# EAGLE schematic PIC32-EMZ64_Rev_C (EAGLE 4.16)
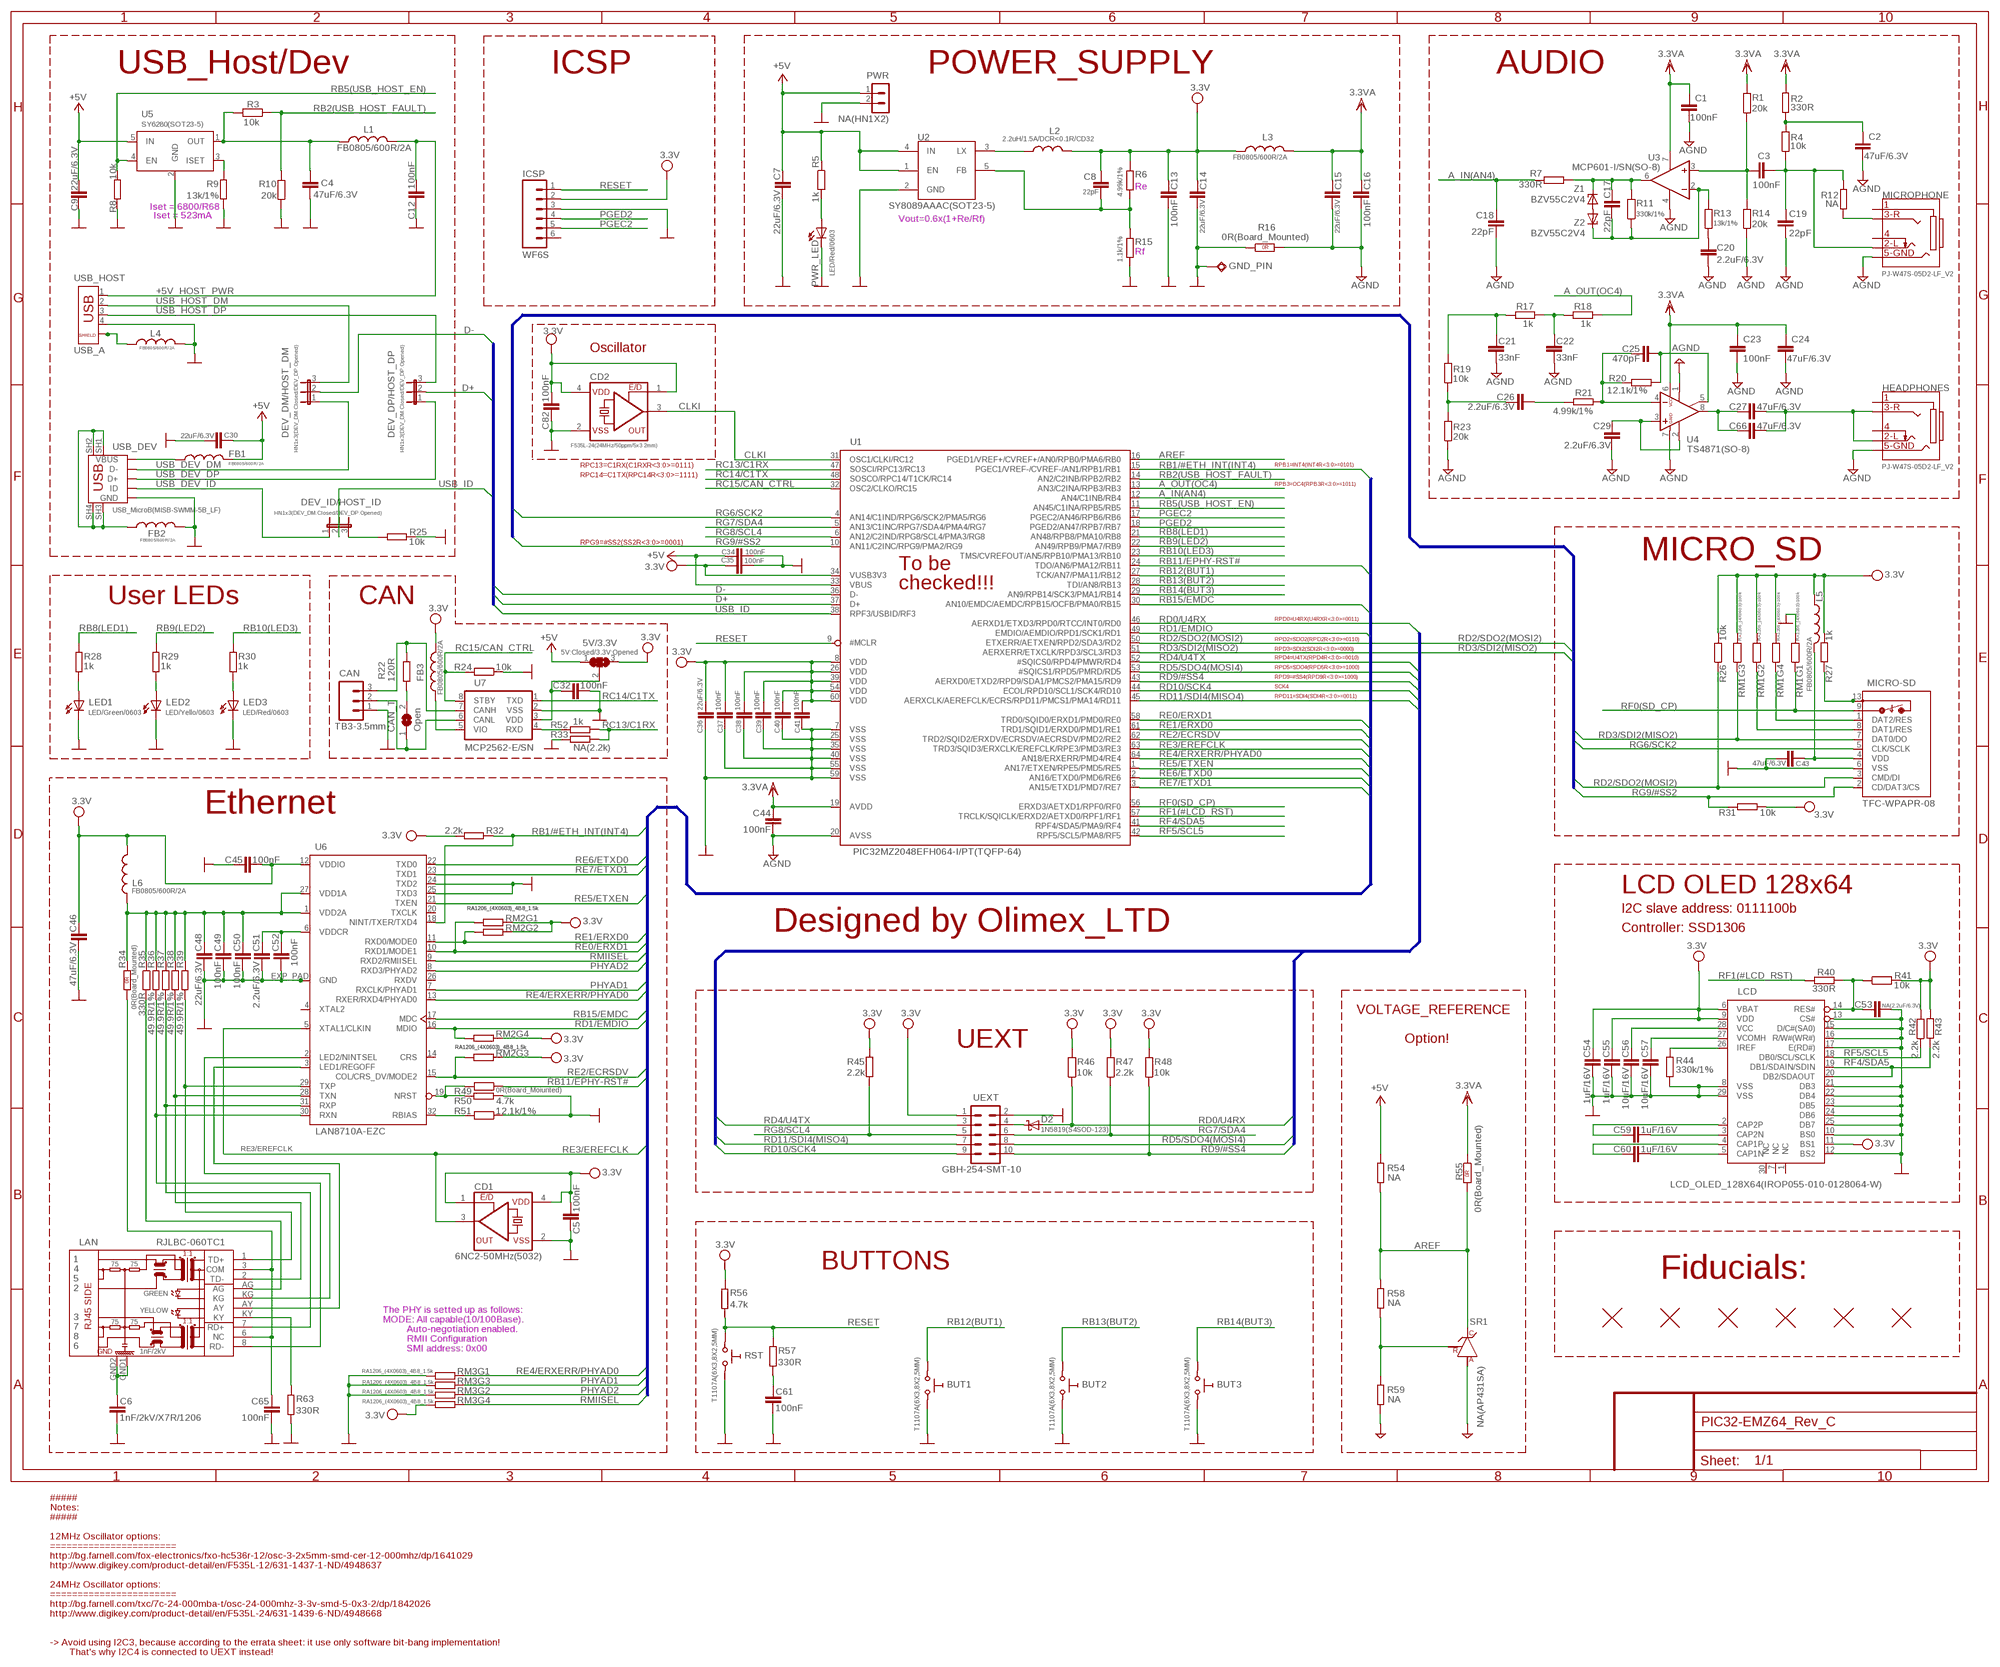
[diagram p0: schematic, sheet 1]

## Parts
5V/3.3V  5V:Closed/3.3V:Opened  SJ2W7  [SJ_2_SMALLER_12_TIED]
BUT1  T1107A(6X3,8X2,5MM)  SW-TAKTT1107A(6X3,8X2,5MM)  [WS-TAKT_6X3.5_SMD_NOCREAM]
BUT2  T1107A(6X3,8X2,5MM)  SW-TAKTT1107A(6X3,8X2,5MM)  [WS-TAKT_6X3.5_SMD_NOCREAM]
BUT3  T1107A(6X3,8X2,5MM)  SW-TAKTT1107A(6X3,8X2,5MM)  [WS-TAKT_6X3.5_SMD_NOCREAM]
C1  100nF  C-EUC0402_SMALL  [C0402_SMALL]
C2  47uF/6.3V  C-EUC0805_5MIL_DWS  [C0805_5MIL_DWS]
C3  100nF  C-EUC0402_SMALL  [C0402_SMALL]
C4  47uF/6.3V  C-EUC0805_5MIL_DWS  [C0805_5MIL_DWS]
C5  100nF  C-EUC0402_SMALL  [C0402_SMALL]
C6  1nF/2kV/X7R/1206  C-EUC1206_5MILS_WS_ISO  [C1206_5MILS_WS_ISO]
C7  22uF/6.3V  C-EUC0603_DWS  [C0603_DWS]
C8  22pF  C-EUC0402_SMALL  [C0402_SMALL]
C9  22uF/6.3V  C-EUC0603_DWS  [C0603_DWS]
C12  100nF  C-EUC0402_SMALL  [C0402_SMALL]
C13  100nF  C-EUC0402_SMALL  [C0402_SMALL]
C14  22uF/6.3V  C-EUC0603_DWS  [C0603_DWS]
C15  22uF/6.3V  C-EUC0603_DWS  [C0603_DWS]
C16  100nF  C-EUC0402_SMALL  [C0402_SMALL]
C17  22pF  C-EUC0402_SMALL  [C0402_SMALL]
C18  22pF  C-EUC0402_SMALL  [C0402_SMALL]
C19  22pF  C-EUC0402_SMALL  [C0402_SMALL]
C20  2.2uF/6.3V  C-EUC0603_DWS  [C0603_DWS]
C21  33nF  C-EUC0402_SMALL  [C0402_SMALL]
C22  33nF  C-EUC0402_SMALL  [C0402_SMALL]
C23  100nF  C-EUC0402_SMALL  [C0402_SMALL]
C24  47uF/6.3V  C-EUC0805_5MIL_DWS  [C0805_5MIL_DWS]
C25  470pF  C-EUC0603_DWS  [C0603_DWS]
C26  2.2uF/6.3V  C-EUC0603_DWS  [C0603_DWS]
C27  47uF/6.3V  C-EUC0805_5MIL_DWS  [C0805_5MIL_DWS]
C29  2.2uF/6.3V  C-EUC0603_DWS  [C0603_DWS]
C30  22uF/6.3V  C-EUC0603_DWS  [C0603_DWS]
C32  100nF  C-EUC0402_SMALL  [C0402_SMALL]
C34  100nF  C-EUC0402_SMALL  [C0402_SMALL]
C35  100nF  C-EUC0402_SMALL  [C0402_SMALL]
C36  22uF/6.3V  C-EUC0603_DWS  [C0603_DWS]
C37  100nF  C-EUC0402_SMALL  [C0402_SMALL]
C38  100nF  C-EUC0402_SMALL  [C0402_SMALL]
C39  100nF  C-EUC0402_SMALL  [C0402_SMALL]
C40  100nF  C-EUC0402_SMALL  [C0402_SMALL]
C41  100nF  C-EUC0402_SMALL  [C0402_SMALL]
C43  47uF/6.3V  C-EUC0805_5MIL_DWS  [C0805_5MIL_DWS]
C44  100nF  C-EUC0402_SMALL  [C0402_SMALL]
C45  100nF  C-EUC0402_SMALL  [C0402_SMALL]
C46  47uF/6.3V  C-EUC0805_5MIL_DWS  [C0805_5MIL_DWS]
C48  22uF/6.3V  C-EUC0603_DWS  [C0603_DWS]
C49  100nF  C-EUC0402_SMALL  [C0402_SMALL]
C50  100nF  C-EUC0402_SMALL  [C0402_SMALL]
C51  2.2uF/6.3V  C-EUC0603_DWS  [C0603_DWS]
C52  100nF  C-EUC0402_SMALL  [C0402_SMALL]
C53  NA(2.2uF/6.3V)  C-EUC0603_DWS  [C0603_DWS]
C54  1uF/16V  C-EUC0805_5MIL_DWS  [C0805_5MIL_DWS]
C55  1uF/16V  C-EUC0805_5MIL_DWS  [C0805_5MIL_DWS]
C56  10uF/16V  C-EUC0805_5MIL_DWS  [C0805_5MIL_DWS]
C57  10uF/16V  C-EUC0805_5MIL_DWS  [C0805_5MIL_DWS]
C59  1uF/16V  C-EUC0805_5MIL_DWS  [C0805_5MIL_DWS]
C60  1uF/16V  C-EUC0805_5MIL_DWS  [C0805_5MIL_DWS]
C61  100nF  C-EUC0402_SMALL  [C0402_SMALL]
C65  100nF  C-EUC0402_SMALL  [C0402_SMALL]
C66  47uF/6.3V  C-EUC0805_5MIL_DWS  [C0805_5MIL_DWS]
C82  100nF  C-EUC0402_SMALL  [C0402_SMALL]
CAN  TB3-3.5mm  CON33.5MM  [CON3/3.5MM]
CAN_T  Open  SJSJ_SMALLER  [SJ_1_SMALLER]
CD1  6NC2-50MHz(5032)  6NC2_CLOCK_DRIVER5032_4P  [5032-4P_HCX-3S]
CD2  F535L-24(24MHz/50ppm/5x3.2mm)  6NC2_CLOCK_DRIVER5032_4P  [5032-4P_HCX-3S]
D2  1N5819(S4SOD-123)  SCHOTKKY7.62SS-1N5819(S4SOD-123)  [SOD-123]
DEV_DM/HOST_DM  HN1x3(DEV_DM:Closed/DEV_DP:Opened)  JP2E  [JP2]
DEV_DP/HOST_DP  HN1x3(DEV_DM:Closed/DEV_DP:Opened)  JP2E  [JP2]
DEV_ID/HOST_ID  HN1x3(DEV_DM:Closed/DEV_DP:Opened)  JP2E  [JP2]
FB1  FB0805/600R/2A  L-USL0805_5MIL_DWS  [L0805_5MIL_DWS]
FB2  FB0805/600R/2A  L-USL0805_5MIL_DWS  [L0805_5MIL_DWS]
FB3  FB0805/600R/2A  L-USL0805_5MIL_DWS  [L0805_5MIL_DWS]
FID1  FIDUCIAL  [FIDUCIAL-1X3]
FID2  FIDUCIAL  [FIDUCIAL-1X3]
FID3  FIDUCIAL  [FIDUCIAL-1X3]
FID4  FIDUCIAL  [FIDUCIAL-1X3]
FID5  FIDUCIAL  [FIDUCIAL-1X3]
FID6  FIDUCIAL  [FIDUCIAL-1X3]
GND_PIN  TESTPAD3  [TEST_PAD40/70/SQUARE]
HEADPHONES  PJ-W47S-05D2-LF_V2  AUDIO_JACK_5PINPJ-W47S-05D2-LF_V2  [PJ-W47S-05D2-LF_5PIN_V2]
ICSP  WF6S  CON62.54-0-D  [CON2.54MM-6-0D]
L1  FB0805/600R/2A  L-USL0805_5MIL_DWS  [L0805_5MIL_DWS]
L2  2.2uH/1.5A/DCR<0.1R/CD32  L-CD32  [CD32]
L3  FB0805/600R/2A  L-USL0805_5MIL_DWS  [L0805_5MIL_DWS]
L4  FB0805/600R/2A  L-USL0805_5MIL_DWS  [L0805_5MIL_DWS]
L5  FB0805/600R/2A  L-USL0805_5MIL_DWS  [L0805_5MIL_DWS]
L6  FB0805/600R/2A  L-USL0805_5MIL_DWS  [L0805_5MIL_DWS]
LAN  RJLBC-060TC1  RJLBC-060TC1_GND_MILLING  [RJLBC-060TC1_MILLING]
LCD  LCD_OLED_128X64(IROP055-010-0128064-W)  LCD_OLED_128X64(IROP055-010-0128064-W)-BOTTOM_CONTACTS_DRILLING  [IROP055-010-0128064-W(BOTTOM_CONTACTS_DRILLING)]
LED1  LED/Green/0603  LEDLED-0603_TEST  [LED-0603_TEST]
LED2  LED/Yello/0603  LEDLED-0603_TEST  [LED-0603_TEST]
LED3  LED/Red/0603  LEDLED-0603_TEST  [LED-0603_TEST]
MICRO-SD  TFC-WPAPR-08  MICRO_SD/MMC_CP_NEWTFC-WPAPR-08  [TFC-WPAPR-08]
MICROPHONE  PJ-W47S-05D2-LF_V2  AUDIO_JACK_5PINPJ-W47S-05D2-LF_V2  [PJ-W47S-05D2-LF_5PIN_V2]
PWR  NA(HN1X2)  CON2HN1X2  [HN1X2]
PWR_LED  LED/Red/0603  LEDLED-0603_TEST  [LED-0603_TEST]
R1  20k  R-EU_R0402_SMALL  [R0402_SMALL]
R2  330R  R-EU_R0402_SMALL  [R0402_SMALL]
R3  10k  R-EU_R0402_SMALL  [R0402_SMALL]
R4  10k  R-EU_R0402_SMALL  [R0402_SMALL]
R5  1k  R-EU_R0402_SMALL  [R0402_SMALL]
R6  4.99k/1%  R-EU_R0402_SMALL  [R0402_SMALL]
R7  330R  R-EU_R0402_SMALL  [R0402_SMALL]
R8  10k  R-EU_R0402_SMALL  [R0402_SMALL]
R9  13k/1%  R-EU_R0402_SMALL  [R0402_SMALL]
R10  20k  R-EU_R0402_SMALL  [R0402_SMALL]
R11  330k/1%  R-EU_R0603_5MIL_DWS  [R0603_5MIL_DWS]
R12  NA  R-EU_R0402_SMALL  [R0402_SMALL]
R13  13k/1%  R-EU_R0402_SMALL  [R0402_SMALL]
R14  20k  R-EU_R0402_SMALL  [R0402_SMALL]
R15  1.1k/1%  R-EU_R0603_5MIL_DWS  [R0603_5MIL_DWS]
R16  0R(Board_Mounted)  R_0R0R(NA)  [0603_0R]
R17  1k  R-EU_R0402_SMALL  [R0402_SMALL]
R18  1k  R-EU_R0402_SMALL  [R0402_SMALL]
R19  10k  R-EU_R0402_SMALL  [R0402_SMALL]
R20  12.1k/1%  R-EU_R0603_5MIL_DWS  [R0603_5MIL_DWS]
R21  4.99k/1%  R-EU_R0402_SMALL  [R0402_SMALL]
R22  120R  R-EU_R1206_5MIL_WS  [R1206_5MIL_WS]
R23  20k  R-EU_R0402_SMALL  [R0402_SMALL]
R24  10k  R-EU_R0402_SMALL  [R0402_SMALL]
R25  10k  R-EU_R0402_SMALL  [R0402_SMALL]
R26  10k  R-EU_R0402_SMALL  [R0402_SMALL]
R27  1k  R-EU_R0402_SMALL  [R0402_SMALL]
R28  1k  R-EU_R0402_SMALL  [R0402_SMALL]
R29  1k  R-EU_R0402_SMALL  [R0402_SMALL]
R30  1k  R-EU_R0402_SMALL  [R0402_SMALL]
R31  10k  R-EU_R0402_SMALL  [R0402_SMALL]
R32  2.2k  R-EU_R0402_SMALL  [R0402_SMALL]
R33  NA(2.2k)  R-EU_R0402_SMALL  [R0402_SMALL]
R34  0R(Board_Mounted)  R_0R0R(NA)  [0603_0R]
R35  330R  R-EU_R0402_SMALL  [R0402_SMALL]
R36  49.9R/1%  R-EU_R0402_SMALL  [R0402_SMALL]
R37  49.9R/1%  R-EU_R0402_SMALL  [R0402_SMALL]
R38  49.9R/1%  R-EU_R0402_SMALL  [R0402_SMALL]
R39  49.9R/1%  R-EU_R0402_SMALL  [R0402_SMALL]
R40  330R  R-EU_R0402_SMALL  [R0402_SMALL]
R41  10k  R-EU_R0402_SMALL  [R0402_SMALL]
R42  2.2k  R-EU_R0402_SMALL  [R0402_SMALL]
R43  2.2k  R-EU_R0402_SMALL  [R0402_SMALL]
R44  330k/1%  R-EU_R0603_5MIL_DWS  [R0603_5MIL_DWS]
R45  2.2k  R-EU_R0402_SMALL  [R0402_SMALL]
R46  10k  R-EU_R0402_SMALL  [R0402_SMALL]
R47  2.2k  R-EU_R0402_SMALL  [R0402_SMALL]
R48  10k  R-EU_R0402_SMALL  [R0402_SMALL]
R49  0R(Board_Moiunted)  R-EU_R0402_TI_0R  [R0402_TI_0R]
R50  4.7k  R-EU_R0402_SMALL  [R0402_SMALL]
R51  12.1k/1%  R-EU_R0603_5MIL_DWS  [R0603_5MIL_DWS]
R52  1k  R-EU_R0402_SMALL  [R0402_SMALL]
R54  NA  R-EU_R0402_SMALL  [R0402_SMALL]
R55  0R(Board_Mounted)  R_0R0R(NA)  [0603_0R]
R56  4.7k  R-EU_R0402_SMALL  [R0402_SMALL]
R57  330R  R-EU_R0402_SMALL  [R0402_SMALL]
R58  NA  R-EU_R0402_SMALL  [R0402_SMALL]
R59  NA  R-EU_R0402_SMALL  [R0402_SMALL]
R63  330R  R-EU_R0402_SMALL  [R0402_SMALL]
RM1  RA1206_(4X0603)-100k  R_MATRIX_4E  [R_MATRIX_4]
RM2  RA1206_(4X0603)_4B8_1.5k  R_MATRIX_4E  [R_MATRIX_4]
RM3  RA1206_(4X0603)_4B8_1.5k  R_MATRIX_4E  [R_MATRIX_4]
RST  T1107A(6X3,8X2,5MM)  SW-TAKTT1107A(6X3,8X2,5MM)  [WS-TAKT_6X3.5_SMD_NOCREAM]
SR1  NA(AP431SA)  TL431'''  [SOT-23]
U1  PIC32MZ2048EFH064-I/PT(TQFP-64)  PIC32MZ0512EFE064-I/PT(TQFP-64)  [TQFP64-1]
U2  SY8089AAAC(SOT23-5)  SY8008  [SOT23-5]
U3  MCP601-I/SN(SO-8)  1AMP_P7+4D  [SO08]
U4  TS4871(SO-8)  TS4871SO-8  [SO-8]
U5  SY6280(SOT23-5)  SY6280  [SOT23-5]
U6  LAN8710A-EZC  [QFN-32(DRILLS)]
U7  MCP2562-E/SN  [SO-08_THIN]
UEXT  GBH-254-SMT-10  ML10MD  [ML10_S]
USB_DEV  USB_MicroB(MISB-SWMM-5B_LF)  MINI_USB95P/F_TYPEB_DIP/A01SB141B1-261  [MICRO_USB_5P/F_TYPEB_DIP]
USB_HOST  USB_A  USB_SHIELD3  [USB_PN87520_HOST_PTH]
Z1  BZV55C2V4  ZENER-DIODESOD80C  [SOD80C]
Z2  BZV55C2V4  ZENER-DIODESOD80C  [SOD80C]

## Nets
+5V: 5V/3.3V.1 C7.1 C9.1 C30.1 C34.2 FB1.1 PWR.1 R5.1 R54.2 U1.33(VBUS) U2.1(EN) U2.4(IN) U5.5(IN)
+5V_HOST_PWR: C12.1 L1.1 USB_HOST.1
A_IN(AN4): C18.1 R7.2 U1.12(AN4/C1INB/RB4)
A_OUT(OC4): R18.1 U1.13(AN3/C2INA/RPB3/RB3)
AGND: C1.2 C2.2 C15.2 C16.2 C18.2 C19.2 C20.2 C21.2 C22.2 C23.2 C24.2 C29.2 C44.2 HEADPHONES.5 MICROPHONE.5 R14.1 R16.2(1.2) R23.1 R59.1 SR1.3(A) U1.20(AVSS) U3.4(V-) U4.1(STANDBY) U4.7(GND)
AREF: R54.1 R55.2(1.2) R58.2 SR1.1(C) U1.16(PGED1/VREF+/CVREF+/AN0/RPB0/PMA6/RB0)
CANH: CAN.3 R22.2 U7.7(CANH)
CANL: CAN.2 CAN_T.1 U7.6(CANL)
CLKI: CD2.3(OUT) U1.31(OSC1/CLKI/RC12)
D+: DEV_DP/HOST_DP.2 U1.37(D+)
D-: DEV_DM/HOST_DM.2 U1.36(D-)
ETH_SHIELD: C6.2 LAN.GND1 LAN.GND2
GND [PWR]: BUT1.P$2 BUT2.P$2 BUT3.P$2 C4.2 C5.2 C6.1 C7.2 C9.2 C12.2 C13.2 C14.2 C30.2 C32.2 C34.1 C35.1 C36.2 C37.2 C38.2 C39.2 C40.2 C41.2 C43.2 C45.1 C46.1 C48.1 C49.1 C50.1 C51.1 C52.1 C53.2 C54.1 C55.1 C56.1 C57.1 C61.2 C65.1 C82.2 CAN.1 CD1.2(VSS) CD2.2(VSS) FB2.1 GND_PIN.P$1(PP) ICSP.3 L4.1 LCD.8(VSS) LCD.10(BS0) LCD.12(BS2) LCD.13(CS#) LCD.15(D/C#(SA0)) LCD.16(R/W#(WR#)) LCD.17(E(RD#)) LCD.21(DB3) LCD.22(DB4) LCD.23(DB5) LCD.24(DB6) LCD.25(DB7) LCD.29(VSS) LED1.C LED2.C LED3.C MICRO-SD.6(VSS) PWR.2 PWR_LED.C R8.1 R9.1 R10.1 R15.2 R16.1(1.1) R24.1 R25.1 R33.2 R44.1 R50.1 R51.1 R63.2 RM1.1.2 RM3.1.2 RM3.2.2 RM3.3.2 RST.P$2 U1.7(VSS) U1.25(VSS) U1.35(VSS) U1.40(VSS) U1.55(VSS) U1.59(VSS) U2.2(GND) U5.2(GND) U6.24(TXD2) U6.25(TXD3) U6.EP1(GND1) U6.EP2(GND2) U6.EP3(GND3) U6.EP4(GND4) U6.EP5(GND5) U6.EP6(GND6) U6.EP7(GND7) U6.EP8(GND8) U6.EP9(GND9) U6.EXP_PAD(GND) U7.2(VSS) UEXT.2 USB_DEV.GND USB_HOST.4
LEFT: C3.1 C19.1 MICROPHONE.2 R4.1 R12.2
MCIDAT1: MICRO-SD.8(DAT1/RES) RM1.2.1
MCIDAT2: MICRO-SD.1(DAT2/RES) RM1.4.1
N$1: 5V/3.3V.2 C32.1 U7.3(VDD)
N$2: DEV_ID/HOST_ID.3 R25.2
N$4: MICRO-SD.10(PACK1) MICRO-SD.11(PACK2) MICRO-SD.12(PACK3) MICRO-SD.13(PACK4) R27.1
N$5: C61.1 R57.1
N$6: FB1.2 USB_DEV.VBUS
N$7: R52.2 U7.4(RXD)
N$8: PWR_LED.A R5.2
N$9: C56.2 LCD.28(VCC)
N$10: C60.1 LCD.4(CAP1P)
N$11: FB3.1 U7.5(VIO)
N$13: C53.1 LCD.14(RES#) R40.2 R41.1
N$14: C25.2 R20.1 R21.2 U4.4(-IN)
N$15: C29.1 U4.2(BYPASS) U4.3(+IN)
N$16: C27.1 C66.1 U4.8(OUT2)
N$17: D2.C UEXT.4
N$18: C21.1 R17.2 R19.2
N$22: C22.1 R17.1 R18.2
N$23: LED1.A R28.1
N$24: C25.1 R20.2 U4.5(OUT1)
N$25: C26.1 R21.1
N$26: LED2.A R29.1
N$27: LED3.A R30.1
N$31: R49.2 R50.2 U6.19(NRST)
N$32: LCD.26(IREF) R44.2
N$36: R58.1 R59.2 SR1.2(R)
N$37: C59.1 LCD.2(CAP2P)
N$39: C59.2 LCD.3(CAP2N)
N$40: C60.2 LCD.5(CAP1N)
N$41: LAN.1(TD+) R39.1 U6.29(TXP)
N$42: LAN.2(TD-) R38.1 U6.28(TXN)
N$44: LAN.7(RD+) R37.1 U6.31(RXP)
N$49: LAN.8(RD-) R36.1 U6.30(RXN)
N$53: LAN.KG U6.2(LED2/NINTSEL)
N$54: LAN.AY U6.3(LED1/REGOFF)
N$55: R51.2 U6.32(RBIAS)
N$56: C65.2 LAN.3(COM) LAN.6(NC) R34.1(1.1)
N$57: LAN.KY R63.1
N$58: C51.2 C52.2 U6.6(VDDCR)
N$59: C48.2 C49.2 C50.2 L6.1 R34.2(1.2) R35.1 R36.2 R37.2 R38.2 R39.2 U6.1(VDD2A) U6.27(VDD1A)
N$64: L2.1 U2.3(LX)
N$65: LAN.AG R35.2
N$66: C8.2 R6.2 R15.1 U2.5(FB)
N$75: CAN_T.2 R22.1
N$115: R9.2 U5.3(ISET)
N$116: C43.1 L5.2 MICRO-SD.4(VDD)
N$137: C4.1 L1.2 R3.2 U5.1(OUT)
N$266: L4.2 USB_HOST.P$1 USB_HOST.P$2
N$550: C3.2 R1.1 R14.2 U3.3(+IN)
N$553: C2.1 R2.1 R4.2
N$554: C17.2 R11.1 R13.2 U3.2(-IN) Z2.C
N$555: C20.1 R13.1
N$556: C17.1 R7.1 R11.2 U3.6(OUT) Z1.C
N$557: Z1.A Z2.A
N$559: C27.2 C66.2 HEADPHONES.2 HEADPHONES.3
N$561: C26.2 R19.1 R23.2
PGEC2: ICSP.5 U1.17(PGEC2/AN46/RPB6/RB6)
PGED2: ICSP.4 U1.18(PGED2/AN47/RPB7/RB7)
PHYAD1: RM3.3.1 U6.7(RXCLK/PHYAD1)
PHYAD2: RM3.2.1 U6.8(RXD3/PHYAD2)
RB1/#ETH_INT(INT4): R32.1 U1.15(PGEC1/VREF-/CVREF-/AN1/RPB1/RB1) U6.18(NINT/TXER/TXD4)
RB2(USB_HOST_FAULT): R3.1 R10.2 U1.14(AN2/C2INB/RPB2/RB2)
RB5(USB_HOST_EN): R8.2 U1.11(AN45/C1INA/RPB5/RB5) U5.4(EN)
RB8(LED1): R28.2 U1.21(AN48/RPB8/PMA10/RB8)
RB9(LED2): R29.2 U1.22(AN49/RPB9/PMA7/RB9)
RB10(LED3): R30.2 U1.23(TMS/CVREFOUT/AN5/RPB10/PMA13/RB10)
RB11/EPHY-RST#: R49.1 U1.24(TDO/AN6/PMA12/RB11)
RB12(BUT1): BUT1.P$1 U1.27(TCK/AN7/PMA11/RB12)
RB13(BUT2): BUT2.P$1 U1.28(TDI/AN8/RB13)
RB14(BUT3): BUT3.P$1 U1.29(AN9/RPB14/SCK3/PMA1/RB14)
RB15/EMDC: U1.30(AN10/EMDC/AEMDC/RPB15/OCFB/PMA0/RB15) U6.17(MDC)
RC13/C1RX: R33.1 R52.1 U1.47(SOSCI/RPC13/RC13)
RC14/C1TX: U1.48(SOSCO/RPC14/T1CK/RC14) U7.1(TXD)
RC15/CAN_CTRL: R24.2 U1.32(OSC2/CLKO/RC15) U7.8(STBY)
RD0/U4RX: D2.A R46.1 U1.46(AERXD1/ETXD3/RPD0/RTCC/INT0/RD0)
RD1/EMDIO: RM2.4.2 U1.49(EMDIO/AEMDIO/RPD1/SCK1/RD1) U6.16(MDIO)
RD2/SDO2(MOSI2): MICRO-SD.3(CMD/DI) R26.1 U1.50(ETXERR/AETXEN/RPD2/SDA3/RD2)
RD3/SDI2(MISO2): MICRO-SD.7(DAT0/DO) RM1.3.1 U1.51(AERXERR/ETXCLK/RPD3/SCL3/RD3)
RD4/U4TX: U1.52(#SQICS0/RPD4/PMWR/RD4) UEXT.3
RD5/SDO4(MOSI4): U1.53(#SQICS1/RPD5/PMRD/RD5) UEXT.8
RD9/#SS4: R48.1 U1.43(AERXD0/ETXD2/RPD9/SDA1/PMCS2/PMA15/RD9) UEXT.10
RD10/SCK4: U1.44(ECOL/RPD10/SCL1/SCK4/RD10) UEXT.9
RD11/SDI4(MISO4): U1.45(AERXCLK/AEREFCLK/ECRS/RPD11/PMCS1/PMA14/RD11) UEXT.7
RE0/ERXD1: RM2.1.2 U1.58(TRD0/SQID0/ERXD1/PMD0/RE0) U6.10(RXD1/MODE1)
RE1/ERXD0: RM2.2.2 U1.61(TRD1/SQID1/ERXD0/PMD1/RE1) U6.11(RXD0/MODE0)
RE2/ECRSDV: RM2.3.2 U1.62(TRD2/SQID2/ERXDV/ECRSDV/AECRSDV/PMD2/RE2) U6.15(COL/CRS_DV/MODE2)
RE3/EREFCLK: CD1.3(OUT) U1.63(TRD3/SQID3/ERXCLK/EREFCLK/RPE3/PMD3/RE3) U6.5(XTAL1/CLKIN)
RE4/ERXERR/PHYAD0: RM3.1.1 U1.64(AN18/ERXERR/PMD4/RE4) U6.13(RXER/RXD4/PHYAD0)
RE5/ETXEN: U1.1(AN17/ETXEN/RPE5/PMD5/RE5) U6.21(TXEN)
RE6/ETXD0: U1.2(AN16/ETXD0/PMD6/RE6) U6.22(TXD0)
RE7/ETXD1: U1.3(AN15/ETXD1/PMD7/RE7) U6.23(TXD1)
RESET: ICSP.1 R56.2 R57.2 RST.P$1 U1.9(#MCLR)
RF0(SD_CP): MICRO-SD.9(CP_E) RM1.1.1 U1.56(ERXD3/AETXD1/RPF0/RF0)
RF1(#LCD_RST): R40.1 U1.57(TRCLK/SQICLK/ERXD2/AETXD0/RPF1/RF1)
RF4/SDA5: LCD.19(DB1/SDAIN/SDIN) LCD.20(DB2/SDAOUT) R43.1 U1.41(RPF4/SDA5/PMA9/RF4)
RF5/SCL5: LCD.18(DB0/SCL/SCLK) R42.1 U1.42(RPF5/SCL5/PMA8/RF5)
RG6/SCK2: MICRO-SD.5(CLK/SCLK) U1.4(AN14/C1IND/RPG6/SCK2/PMA5/RG6)
RG7/SDA4: R47.1 U1.5(AN13/C1INC/RPG7/SDA4/PMA4/RG7) UEXT.6
RG8/SCL4: R45.1 U1.6(AN12/C2IND/RPG8/SCL4/PMA3/RG8) UEXT.5
RG9/#SS2: MICRO-SD.2(CD/DAT3/CS) R31.1 U1.10(AN11/C2INC/RPG9/PMA2/RG9)
RIGHT: MICROPHONE.3 R12.1
RMIISEL: RM3.4.1 U6.9(RXD2/RMIISEL)
USB_DEV_DM: DEV_DM/HOST_DM.1 USB_DEV.D-
USB_DEV_DP: DEV_DP/HOST_DP.1 USB_DEV.D+
USB_DEV_ID: DEV_ID/HOST_ID.1 USB_DEV.ID
USB_HOST_DM: DEV_DM/HOST_DM.3 USB_HOST.2
USB_HOST_DP: DEV_DP/HOST_DP.3 USB_HOST.3
USB_ID: DEV_ID/HOST_ID.2 U1.38(RPF3/USBID/RF3)
USB_SHIELD: FB2.2 USB_DEV.SH1(GND1) USB_DEV.SH2(GND2) USB_DEV.SH3(GND3) USB_DEV.SH4(GND4)
VCC: 5V/3.3V.3 C5.1 C8.1 C13.1 C14.1 C35.2 C36.1 C37.1 C38.1 C39.1 C40.1 C41.1 C45.2 C46.2 C54.2 C55.2 C82.1 CD1.1(E/D) CD1.4(VDD) CD2.1(E/D) CD2.4(VDD) FB3.2 ICSP.2 L2.2 L3.1 L5.1 L6.2 LCD.6(VBAT) LCD.9(VDD) LCD.11(BS1) R6.1 R26.2 R27.2 R31.2 R32.2 R41.2 R42.2 R43.2 R45.2 R46.2 R47.2 R48.2 R56.1 RM1.2.2 RM1.3.2 RM1.4.2 RM2.1.1 RM2.2.1 RM2.3.1 RM2.4.1 RM3.4.2 U1.8(VDD) U1.26(VDD) U1.34(VUSB3V3) U1.39(VDD) U1.54(VDD) U1.60(VDD) U6.12(VDDIO) UEXT.1 ; supply symbol labelled 3.3V
VCOMH1: C57.2 LCD.27(VCOMH)
VDD: C1.1 C15.1 C16.1 C23.1 C24.1 C44.1 L3.2 R1.2 R2.2 R55.1(1.1) U1.19(AVDD) U3.7(V+) U4.6(VCC) ; supply symbol labelled 3.3VA
Unconnected: HEADPHONES.1 HEADPHONES.4 ICSP.6 LCD.1(NC) LCD.7(NC) LCD.30(NC) MICROPHONE.1 MICROPHONE.4 U6.4(XTAL2) U6.14(CRS) U6.20(TXCLK) U6.26(RXDV)

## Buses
D+,D-,USB_ID
B$1
B$2
B$3

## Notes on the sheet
- USB_Host/Dev | ICSP | POWER_SUPPLY | AUDIO
- Re
- Iset = 6800/R68
- Iset = 523mA
- Vout=0.6x(1+Re/Rf)
- Rf
- Oscillator
- RPC13=C1RX(C1RXR<3:0>=0111) | RPB1=INT4(INT4R<3:0>=0101)
- RPC14=C1TX(RPC14R<3:0>=1111)
- RPB3=OC4(RPB3R<3:0>=1011)
- RPG9=#SS2(SS2R<3:0>=0001)
- MICRO_SD
- User LEDs | CAN
- RPD0=U4RX(U4RXR<3:0>=0011)
- RPD2=SDO2(RPD2R<3:0>=0110)
- RPD3=SDI2(SDI2R<3:0>=0000)
- RPD4=U4TX(RPD4R<3:0>=0010)
- RPD5=SDO4(RPD5R<3:0>=1000)
- RPD9=#SS4(RPD9R<3:0>=1000)
- SCK4
- RPD11=SDI4(SDI4R<3:0>=0011)
- Ethernet
- LCD OLED 128x64
- I2C slave address: 0111100b
- Designed by Olimex_LTD | Controller: SSD1306
- VOLTAGE_REFERENCE
- Option!
- UEXT
- BUTTONS
- Fiducials:
- The PHY is setted up as follows:
- MODE: All capable(10/100Base).
- Auto-negotiation enabled.
- RMII Configuration
- SMI address: 0x00
- #####
- Notes:
- #####
- 12MHz Oscillator options:
- =======================
- http://bg.farnell.com/fox-electronics/fxo-hc536r-12/osc-3-2x5mm-smd-cer-12-000mhz/dp/1641029
- http://www.digikey.com/product-detail/en/F535L-12/631-1437-1-ND/4948637
- 24MHz Oscillator options:
- =======================
- http://bg.farnell.com/txc/7c-24-000mba-t/osc-24-000mhz-3-3v-smd-5-0x3-2/dp/1842026
- http://www.digikey.com/product-detail/en/F535L-24/631-1439-6-ND/4948668
- -> Avoid using I2C3, because according to the errata sheet: it use only software bit-bang implementation!
- That's why I2C4 is connected to UEXT instead!

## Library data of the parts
5V/3.3V = jumper:SJ2W: SMD solder JUMPER
BUT1-BUT3 RST = gogo:SW-TAKT
C1-C9 C12-C27 C29 C30 C32 C34-C41 C43-C46 C48-C57 C59-C61 C65 C66 C82 = rcl:C-EU: CAPACITOR, European symbol
CAN = DOUBLE-SIDE:CON3: CONNECTORS - 3 PINS
CAN_T = jumper:SJ: SMD solder JUMPER
CD1 CD2 = gogo:6NC2_CLOCK_DRIVER
D2 = gogo:SCHOTKKY7.62SS
DEV_DM/HOST_DM DEV_DP/HOST_DP DEV_ID/HOST_ID = jumper:JP2E: JUMPER
FB1-FB3 L1 L3-L6 = rcl:L-US: INDUCTOR, American symbol
FID1-FID6 = SparkFunEagle-6-6-07:FIDUCIAL: Fiducial Alignment Points
GND_PIN = gogo:TESTPAD: drill 40mils, diameter 70mils
HEADPHONES MICROPHONE = gogo:AUDIO_JACK_5PIN
ICSP = DOUBLE-SIDE:CON6: CONNECTORS - 6 PINS
L2 = OLIMEX_DISCRET:L
LAN = OLIMEX_CONNECTORS:RJLBC-060TC1_GND
LCD = olimex_lcd:LCD_OLED_128X64(IROP055-010-0128064-W)
LED1-LED3 PWR_LED = DOUBLE-SIDE:LED
MICRO-SD = OLIMEX_CONNECTORS:MICRO_SD/MMC_CP_NEW
PWR = Penko:CON2
R1-R15 R17-R33 R35-R52 R54 R56-R59 R63 = rcl:R-EU_: RESISTOR, European symbol
R16 R34 R55 = OLIMEX_DISCRET:R_0R
RM1-RM3 = OLIMEX_DISCRET:R_MATRIX_4E
SR1 = OLIMEX_IC:TL431: TL431 Programmable Shunt Regulator Features: -> Programmable Output Voltage to 36 Volts -> Low Dynamic Output Impedance 0.20 Typical -> Sink Current Capability of 1.0 to 100mA -> Equivalent Full-Range Temperature Coefficient of 50ppm/°C Typical -> Temperature Compensated For Operation Over Full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
U1 = OLIMEX_IC:PIC32MZ0512EFE064-I
U2 = OLIMEX_IC:SY8008
U3 = linear:1AMP_P7+4: OP AMP
U4 = OLIMEX_IC:TS4871
U5 = OLIMEX_IC:SY6280
U6 = OLIMEX_IC:LAN8710A: LAN8710A/LAN8710Ai Small Footprint MII/RMII 10/100 Ethernet Transceiver with HP Auto-MDIX and flexPWR® Technology
U7 = OLIMEX_IC:MCP2562
UEXT = con-harting-ml:ML10: HARTING
USB_DEV = OLIMEX_CONNECTORS:MINI_USB9
USB_HOST = OLIMEX_CONNECTORS:USB_SHIELD
Z1 Z2 = diode:ZENER-DIODE: Z-Diode

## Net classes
1 PWR: width 0.203 mm, drill 0.178 mm, clearance 0.381 mm
2 thin: width 0.127 mm, drill 0.127 mm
